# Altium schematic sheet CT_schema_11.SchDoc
size 387 x 278 mm
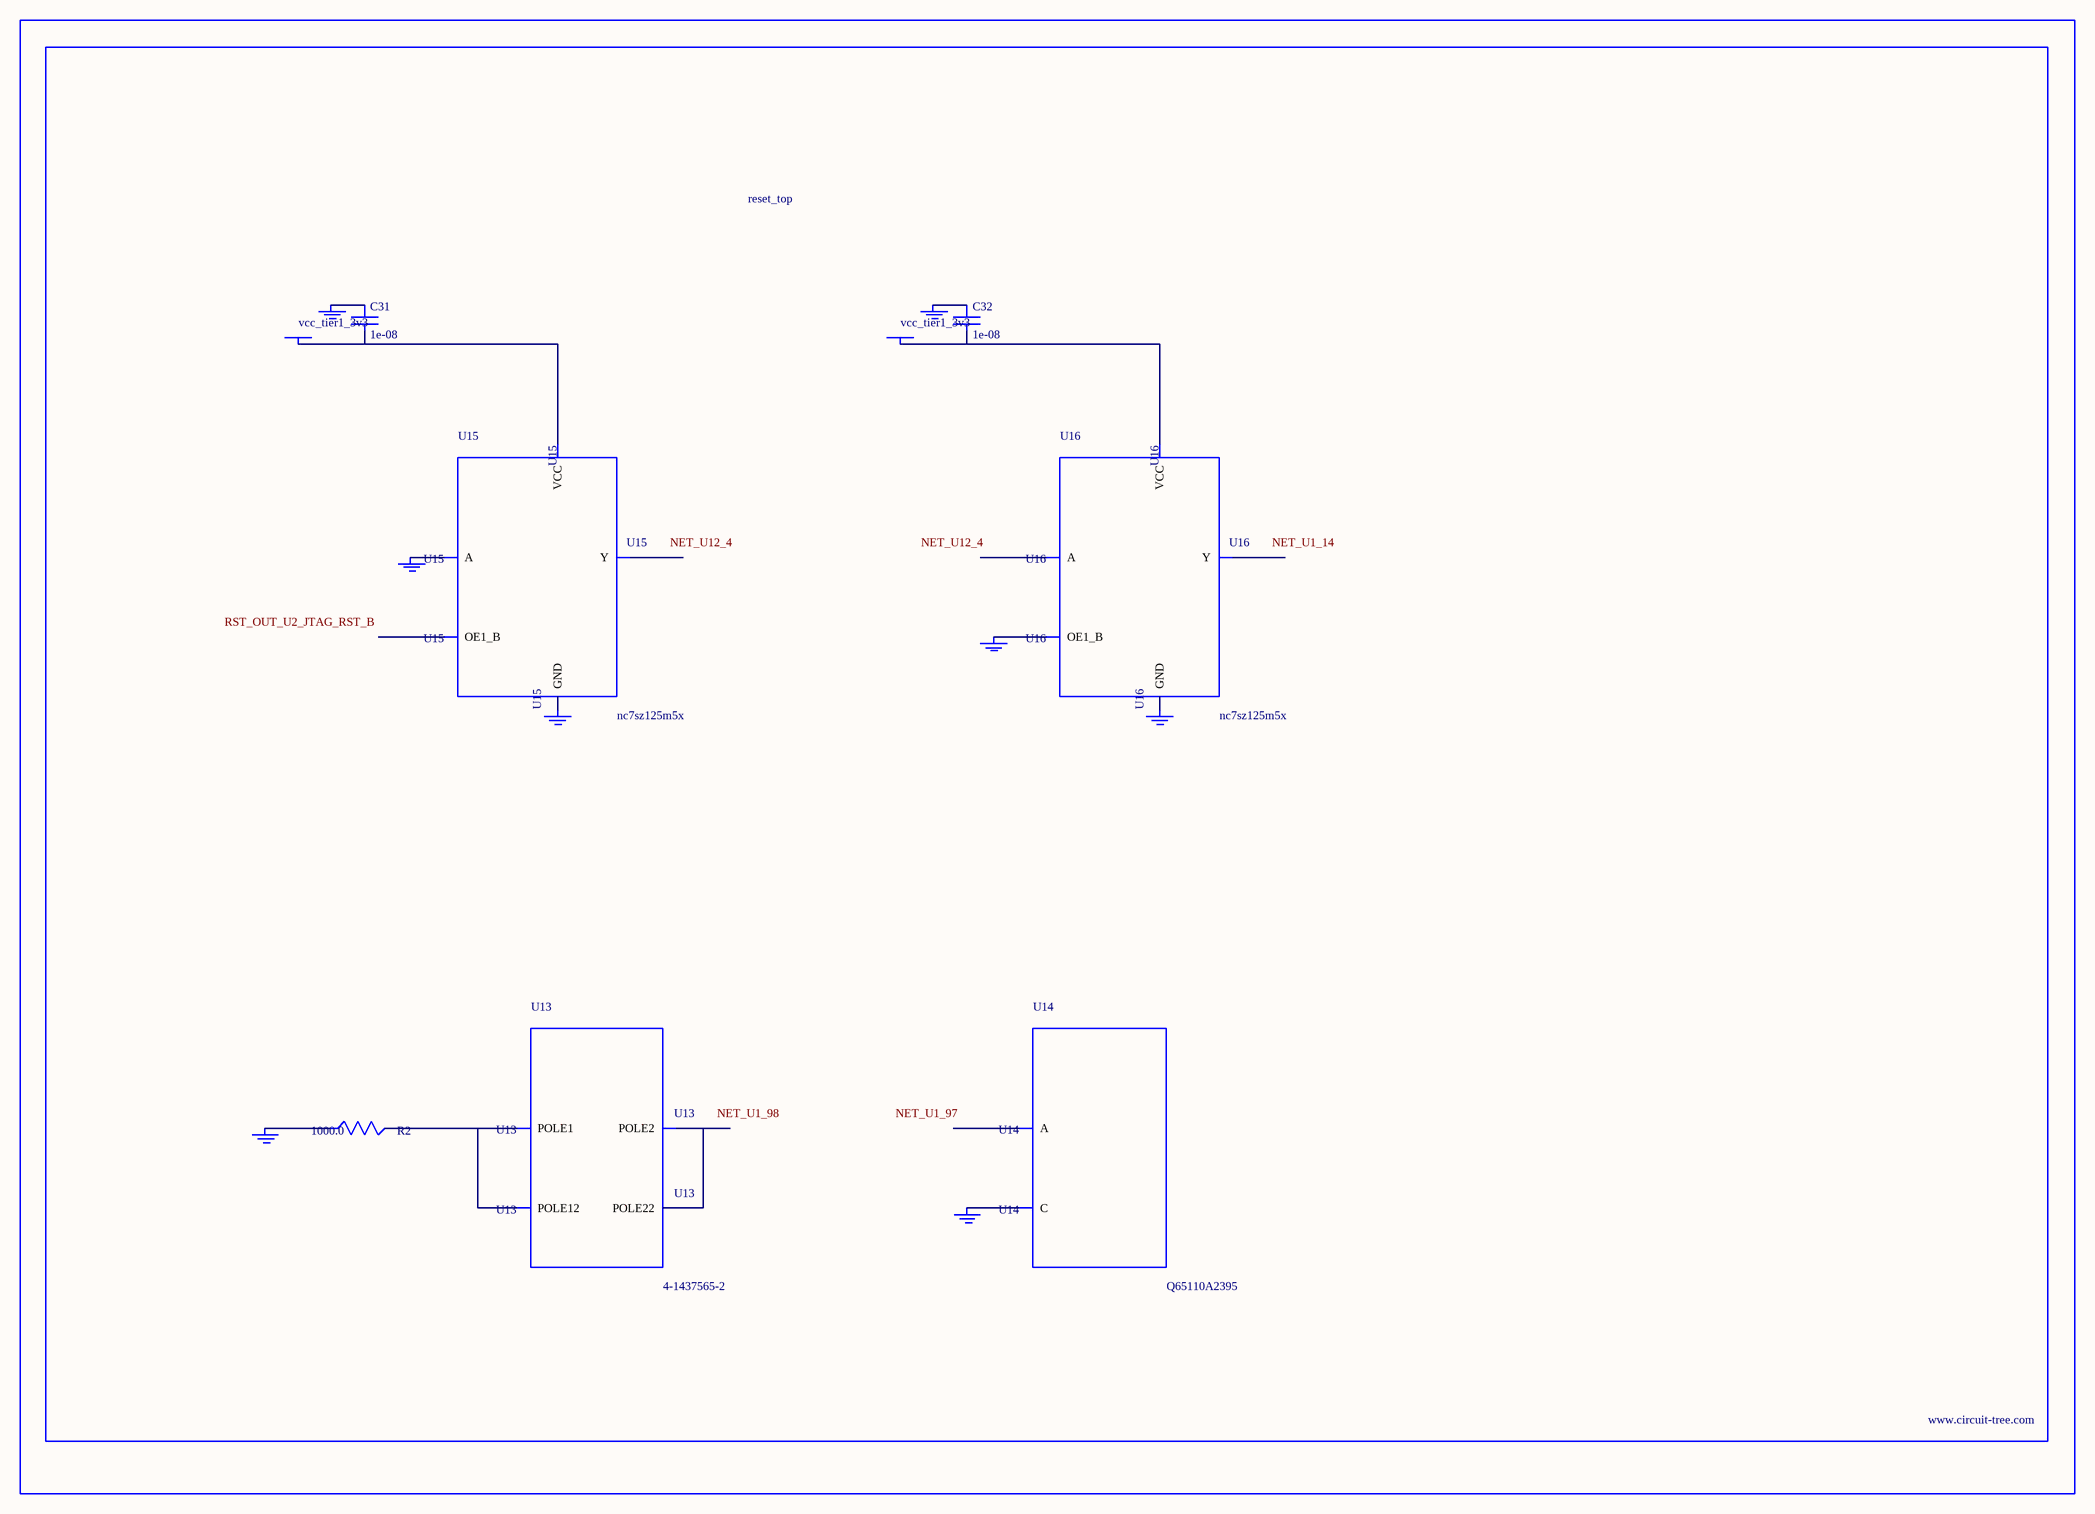
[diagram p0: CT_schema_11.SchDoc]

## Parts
BORDER10  (no value)
C31  1e-08  [C0402]
C32  1e-08  [C0402]
GND_INSTANCE_10_0  (no value)
GND_INSTANCE_10_1  (no value)
GND_INSTANCE_10_2  (no value)
GND_INSTANCE_10_3  (no value)
GND_INSTANCE_10_4  (no value)
GND_INSTANCE_10_5  (no value)
GND_INSTANCE_10_6  (no value)
GND_INSTANCE_10_7  (no value)
POWER_INSTANCE_10_0  vcc_tier1_3v3
POWER_INSTANCE_10_1  vcc_tier1_3v3
R2  1000.0  [R0603]
U13  4-1437565-2  [SW_4-1437565-2]
U14  Q65110A2395  [LGM67K-G1J2-24-Z]
U15  nc7sz125m5x  [NC7SZ125M5X]
U16  nc7sz125m5x  [NC7SZ125M5X]

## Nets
NetC31_1: C31.1 GND_INSTANCE_10_2.0(GND)
NetC31_2: C31.2 POWER_INSTANCE_10_0.0(PWR) U15.5(VCC)
NetC32_1: C32.1 GND_INSTANCE_10_5.0(GND)
NetC32_2: C32.2 POWER_INSTANCE_10_1.0(PWR) U16.5(VCC)
NetGND_INSTANCE_10_0_0: GND_INSTANCE_10_0.0(GND) R2.1
NetGND_INSTANCE_10_1_0: GND_INSTANCE_10_1.0(GND) U14.C
NetGND_INSTANCE_10_3_0: GND_INSTANCE_10_3.0(GND) U15.2(A)
NetGND_INSTANCE_10_4_0: GND_INSTANCE_10_4.0(GND) U15.3(GND)
NetGND_INSTANCE_10_6_0: GND_INSTANCE_10_6.0(GND) U16.1(OE1_B)
NetGND_INSTANCE_10_7_0: GND_INSTANCE_10_7.0(GND) U16.3(GND)
NetR2_2: R2.2 U13.1(POLE1) U13.2(POLE12)
NetU13_3: U13.3(POLE2) U13.4(POLE22)

Not connected (* = marked no-connect by the designer): U14 A; U15 1(OE1_B) 4(Y); U16 2(A) 4(Y)

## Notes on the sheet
- Labels drawn without touching a wire or pin: NET_U1_14, NET_U1_97, NET_U1_98, NET_U12_4, RST_OUT_U2_JTAG_RST_B

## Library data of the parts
BORDER10 = BORDER_PAGE10
C31 C32 = C0402C103K3RAC
GND_INSTANCE_10_0-GND_INSTANCE_10_7 = GND
POWER_INSTANCE_10_0 POWER_INSTANCE_10_1 = PWR
R2 = RC0603JR-071KL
